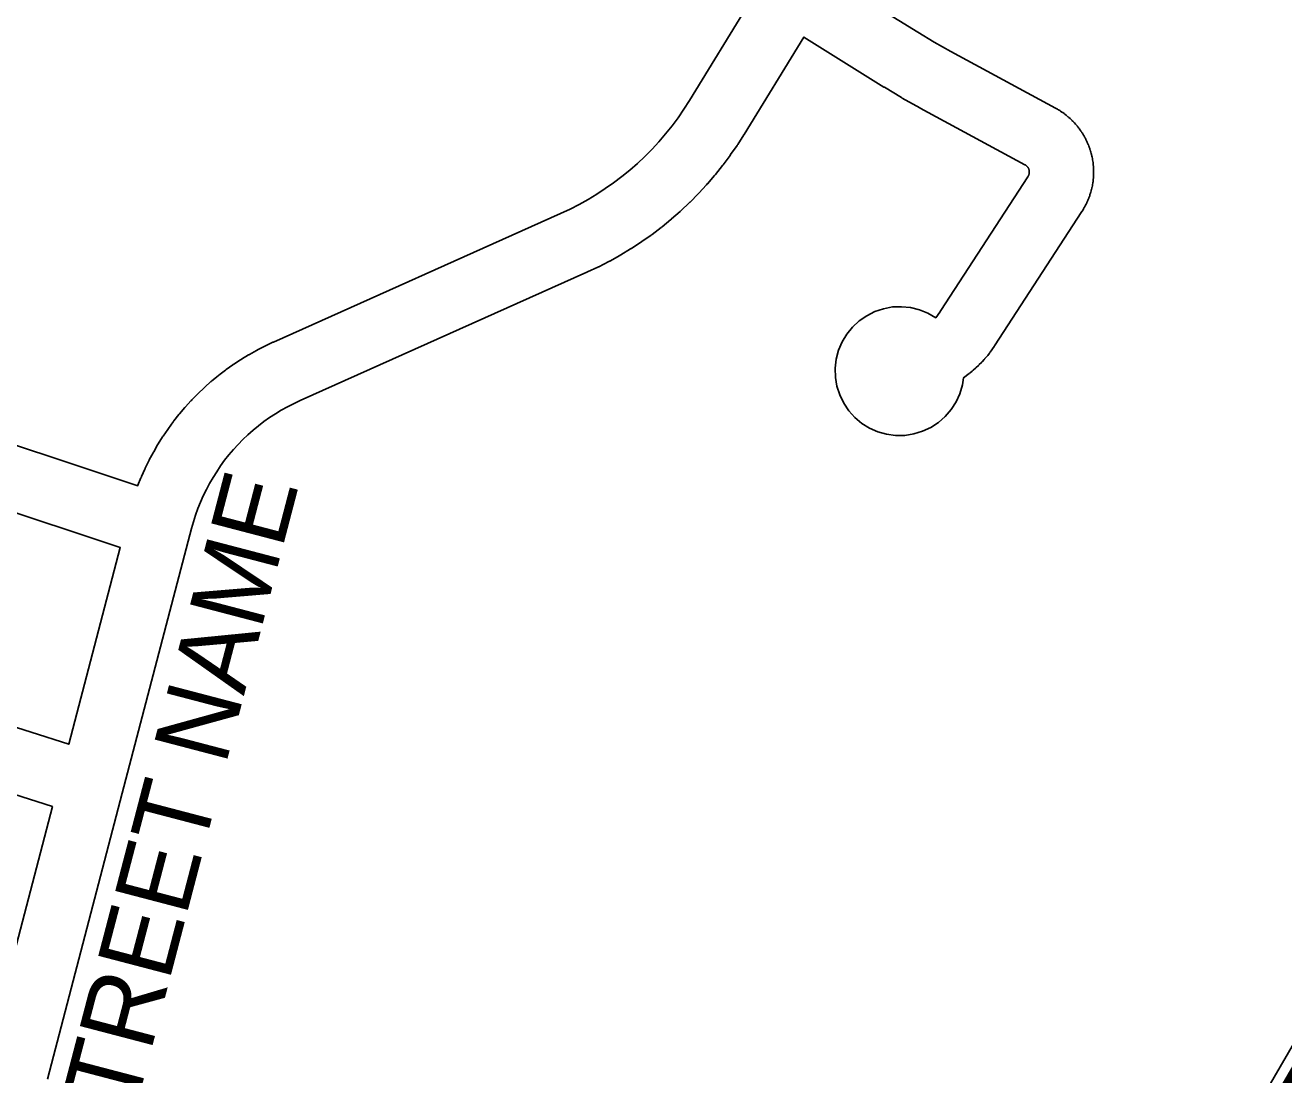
# Model space of a CAD drawing. Extents: x 599744 to 600217, y 4827560 to 4828065.
# Drawn here: x 599995.73 to 600007.45, y 4827978.51 to 4827988.28 of the extents above; entities that cross this region are included whole.
import ezdxf

# ---------------------------------------------------------------- set-up
doc = ezdxf.new("R2010")
doc.units = 0
doc.layers.add('G-ANNO-KEYP', color=7, linetype='Continuous')

msp = doc.modelspace()

# ---------------------------------------------------------------- linework, layer by layer
at = {"layer": 'G-ANNO-KEYP'}
for points in [[(600005.355, 4827987.49), (600005.353, 4827987.49), (600005.346, 4827987.496), (600005.334, 4827987.502), (600005.333, 4827987.502), (600005.329, 4827987.505), (600004.354, 4827988.032), (600004.198, 4827988.119), (600004.044, 4827988.212), (600003.298, 4827988.677), (600005.885, 4827992.881), (600006.372, 4827993.673)], [(600005.355, 4827974.888), (600005.664, 4827975.381), (600005.716, 4827975.467), (600005.764, 4827975.555), (600006.681, 4827977.304), (600006.685, 4827977.31), (600006.685, 4827977.312), (600006.748, 4827977.426), (600006.753, 4827977.433), (600006.753, 4827977.435), (600014.004, 4827989.912)], [(600002.476, 4827988.483), (600001.919, 4827987.578), (600001.866, 4827987.495), (600001.812, 4827987.417), (600001.756, 4827987.341), (600001.696, 4827987.266), (600001.634, 4827987.194), (600001.57, 4827987.125), (600001.503, 4827987.057), (600001.433, 4827986.992), (600001.362, 4827986.929), (600001.288, 4827986.869), (600001.212, 4827986.811), (600001.134, 4827986.757), (600001.055, 4827986.705), (600000.974, 4827986.655), (600000.89, 4827986.609), (600000.806, 4827986.566), (600000.717, 4827986.524), (599998.044, 4827985.329), (599998.042, 4827985.328), (599998.039, 4827985.327), (599997.971, 4827985.295), (599997.968, 4827985.292), (599997.962, 4827985.29), (599997.895, 4827985.256), (599997.891, 4827985.253), (599997.885, 4827985.251), (599997.82, 4827985.214), (599997.815, 4827985.211)], [(600001.567, 4827986.33), (600001.57, 4827986.331), (600001.654, 4827986.395), (600001.66, 4827986.4), (600001.663, 4827986.402), (600001.744, 4827986.469), (600001.75, 4827986.474), (600001.752, 4827986.475), (600001.832, 4827986.545), (600001.838, 4827986.551), (600001.84, 4827986.552), (600001.917, 4827986.624), (600001.923, 4827986.631), (600001.924, 4827986.632), (600001.999, 4827986.707), (600002.005, 4827986.714), (600002.006, 4827986.715), (600002.078, 4827986.792), (600002.084, 4827986.8), (600002.085, 4827986.8), (600002.153, 4827986.88), (600002.16, 4827986.888), (600002.16, 4827986.888), (600002.226, 4827986.971), (600002.229, 4827986.974), (600002.233, 4827986.979), (600002.296, 4827987.064), (600002.296, 4827987.064), (600002.302, 4827987.073), (600002.362, 4827987.159), (600002.362, 4827987.16), (600002.368, 4827987.168), (600002.425, 4827987.257), (600002.425, 4827987.258), (600002.428, 4827987.262), (600002.984, 4827988.167), (600003.73, 4827987.702), (600003.731, 4827987.702), (600003.734, 4827987.7), (600003.893, 4827987.604), (600003.895, 4827987.603), (600003.901, 4827987.599), (600004.063, 4827987.508), (600004.064, 4827987.508), (600004.067, 4827987.506), (600005.042, 4827986.979), (600005.047, 4827986.977), (600005.049, 4827986.975), (600005.051, 4827986.974), (600005.054, 4827986.972)], [(600005.614, 4827987.209), (600005.611, 4827987.213), (600005.609, 4827987.218), (600005.603, 4827987.23), (600005.599, 4827987.235), (600005.598, 4827987.24), (600005.591, 4827987.252), (600005.587, 4827987.256), (600005.585, 4827987.261), (600005.578, 4827987.272), (600005.574, 4827987.277), (600005.572, 4827987.281), (600005.565, 4827987.293), (600005.56, 4827987.297), (600005.559, 4827987.301), (600005.551, 4827987.312), (600005.546, 4827987.317), (600005.544, 4827987.321), (600005.536, 4827987.331), (600005.531, 4827987.337), (600005.529, 4827987.34), (600005.521, 4827987.35), (600005.515, 4827987.356), (600005.514, 4827987.358), (600005.505, 4827987.368), (600005.498, 4827987.374), (600005.497, 4827987.376), (600005.488, 4827987.386), (600005.481, 4827987.392), (600005.48, 4827987.393), (600005.471, 4827987.403), (600005.463, 4827987.409), (600005.463, 4827987.41), (600005.453, 4827987.419), (600005.445, 4827987.426), (600005.444, 4827987.426), (600005.434, 4827987.435), (600005.427, 4827987.44), (600005.426, 4827987.441), (600005.416, 4827987.449), (600005.416, 4827987.449), (600005.416, 4827987.449), (600005.415, 4827987.449), (600005.415, 4827987.449), (600005.407, 4827987.456), (600005.396, 4827987.464), (600005.395, 4827987.464), (600005.387, 4827987.47), (600005.375, 4827987.477), (600005.374, 4827987.478), (600005.367, 4827987.483), (600005.355, 4827987.49)], [(600005.677, 4827986.819), (600005.678, 4827986.832), (600005.678, 4827986.84), (600005.68, 4827986.843), (600005.681, 4827986.856), (600005.681, 4827986.865), (600005.682, 4827986.867), (600005.682, 4827986.88), (600005.682, 4827986.889), (600005.683, 4827986.891), (600005.683, 4827986.905), (600005.683, 4827986.914), (600005.683, 4827986.915), (600005.683, 4827986.929), (600005.682, 4827986.939), (600005.682, 4827986.94), (600005.682, 4827986.953), (600005.681, 4827986.963), (600005.681, 4827986.964), (600005.68, 4827986.977), (600005.679, 4827986.988), (600005.679, 4827986.988), (600005.677, 4827987.001), (600005.677, 4827987.001), (600005.675, 4827987.012), (600005.673, 4827987.025), (600005.673, 4827987.026), (600005.671, 4827987.036), (600005.669, 4827987.049), (600005.668, 4827987.05), (600005.667, 4827987.059), (600005.663, 4827987.073), (600005.663, 4827987.074), (600005.661, 4827987.083), (600005.657, 4827987.096), (600005.656, 4827987.098), (600005.654, 4827987.106), (600005.65, 4827987.119), (600005.649, 4827987.121), (600005.647, 4827987.129), (600005.642, 4827987.142), (600005.641, 4827987.145), (600005.639, 4827987.152), (600005.634, 4827987.165), (600005.631, 4827987.168), (600005.629, 4827987.175), (600005.624, 4827987.187), (600005.622, 4827987.19), (600005.62, 4827987.197), (600005.614, 4827987.209)], [(600005.054, 4827986.972), (600005.056, 4827986.97), (600005.058, 4827986.969), (600005.06, 4827986.967), (600005.062, 4827986.965), (600005.064, 4827986.963), (600005.066, 4827986.961), (600005.067, 4827986.959), (600005.069, 4827986.957), (600005.07, 4827986.955), (600005.072, 4827986.952), (600005.074, 4827986.95), (600005.075, 4827986.948), (600005.076, 4827986.945), (600005.077, 4827986.943), (600005.078, 4827986.941), (600005.079, 4827986.938), (600005.08, 4827986.935), (600005.081, 4827986.933), (600005.082, 4827986.93), (600005.083, 4827986.927), (600005.083, 4827986.925), (600005.083, 4827986.922), (600005.084, 4827986.92), (600005.084, 4827986.916), (600005.084, 4827986.914), (600005.084, 4827986.911), (600005.084, 4827986.909), (600005.084, 4827986.906), (600005.084, 4827986.903), (600005.083, 4827986.9), (600005.083, 4827986.898), (600005.082, 4827986.895), (600005.082, 4827986.892), (600005.081, 4827986.89), (600005.08, 4827986.887), (600005.079, 4827986.885), (600005.078, 4827986.882), (600005.077, 4827986.88), (600005.076, 4827986.877), (600005.075, 4827986.875), (600005.073, 4827986.872), (600005.071, 4827986.868), (600004.26, 4827985.622), (600004.249, 4827985.606), (600004.212, 4827985.555), (600004.139, 4827985.597), (600004.06, 4827985.629), (600003.978, 4827985.65), (600003.893, 4827985.658), (600003.808, 4827985.655), (600003.725, 4827985.639)], [(600004.671, 4827985.175), (600004.689, 4827985.195), (600004.696, 4827985.204), (600004.696, 4827985.204), (600004.713, 4827985.226), (600004.714, 4827985.227), (600004.719, 4827985.234), (600004.736, 4827985.257), (600004.736, 4827985.257), (600004.742, 4827985.266), (600004.757, 4827985.288), (600004.757, 4827985.289), (600004.76, 4827985.293), (600005.574, 4827986.544), (600005.574, 4827986.544), (600005.577, 4827986.548), (600005.584, 4827986.56), (600005.584, 4827986.561), (600005.59, 4827986.569), (600005.596, 4827986.581), (600005.597, 4827986.583), (600005.601, 4827986.59), (600005.608, 4827986.602), (600005.608, 4827986.604), (600005.613, 4827986.612), (600005.619, 4827986.624), (600005.619, 4827986.627), (600005.623, 4827986.633), (600005.628, 4827986.646), (600005.629, 4827986.649), (600005.633, 4827986.656), (600005.638, 4827986.668), (600005.638, 4827986.672), (600005.641, 4827986.678), (600005.646, 4827986.691), (600005.646, 4827986.695), (600005.649, 4827986.701), (600005.653, 4827986.714), (600005.654, 4827986.719), (600005.656, 4827986.724), (600005.66, 4827986.737), (600005.661, 4827986.743), (600005.663, 4827986.748), (600005.666, 4827986.761), (600005.666, 4827986.767), (600005.668, 4827986.771), (600005.671, 4827986.784), (600005.671, 4827986.791), (600005.673, 4827986.795), (600005.675, 4827986.808), (600005.675, 4827986.815), (600005.677, 4827986.819)], [(599995.94, 4827978.468), (599996.636, 4827981.129), (599997.266, 4827983.535), (599997.266, 4827983.535), (599997.281, 4827983.592), (599997.299, 4827983.656), (599997.318, 4827983.718), (599997.34, 4827983.779), (599997.364, 4827983.838), (599997.39, 4827983.897), (599997.419, 4827983.955), (599997.449, 4827984.012), (599997.481, 4827984.068), (599997.515, 4827984.122), (599997.551, 4827984.176), (599997.589, 4827984.228), (599997.629, 4827984.278), (599997.671, 4827984.327), (599997.714, 4827984.375), (599997.759, 4827984.421), (599997.806, 4827984.466), (599997.854, 4827984.508), (599997.904, 4827984.549), (599997.955, 4827984.588), (599998.008, 4827984.626), (599998.062, 4827984.661), (599998.117, 4827984.695), (599998.173, 4827984.726), (599998.23, 4827984.755), (599998.291, 4827984.784), (600000.964, 4827985.979), (600000.966, 4827985.98), (600000.969, 4827985.981), (600001.064, 4827986.026), (600001.068, 4827986.028), (600001.074, 4827986.03), (600001.168, 4827986.078), (600001.172, 4827986.082), (600001.177, 4827986.083), (600001.27, 4827986.135), (600001.274, 4827986.138), (600001.279, 4827986.14), (600001.369, 4827986.195), (600001.374, 4827986.199), (600001.378, 4827986.2), (600001.467, 4827986.258), (600001.471, 4827986.263), (600001.475, 4827986.264), (600001.562, 4827986.325), (600001.567, 4827986.33)], [(600003.725, 4827985.639), (600003.645, 4827985.612), (600003.569, 4827985.574), (600003.499, 4827985.526), (600003.437, 4827985.468), (600003.384, 4827985.402), (600003.34, 4827985.33), (600003.307, 4827985.252), (600003.286, 4827985.17), (600003.276, 4827985.085), (600003.278, 4827985), (600003.292, 4827984.917), (600003.318, 4827984.836), (600003.355, 4827984.76), (600003.402, 4827984.689), (600003.459, 4827984.626), (600003.524, 4827984.572), (600003.596, 4827984.527), (600003.674, 4827984.493), (600003.755, 4827984.47), (600003.839, 4827984.459), (600003.924, 4827984.46), (600004.008, 4827984.473), (600004.089, 4827984.498), (600004.166, 4827984.534), (600004.237, 4827984.58), (600004.301, 4827984.636), (600004.356, 4827984.7), (600004.402, 4827984.771), (600004.437, 4827984.848), (600004.461, 4827984.93), (600004.472, 4827984.997), (600004.523, 4827985.035), (600004.529, 4827985.041), (600004.532, 4827985.042), (600004.553, 4827985.059), (600004.559, 4827985.065), (600004.561, 4827985.066), (600004.582, 4827985.085), (600004.588, 4827985.091), (600004.59, 4827985.092), (600004.61, 4827985.111), (600004.617, 4827985.118), (600004.618, 4827985.119), (600004.637, 4827985.138), (600004.644, 4827985.146), (600004.645, 4827985.146), (600004.664, 4827985.166), (600004.67, 4827985.174), (600004.671, 4827985.175)], [(599996.849, 4827984.151), (599996.845, 4827984.145), (599996.815, 4827984.076), (599996.814, 4827984.072), (599996.81, 4827984.066), (599996.782, 4827983.996), (599996.782, 4827983.992), (599996.781, 4827983.991), (599993.054, 4827985.229)], [(599997.815, 4827985.211), (599997.81, 4827985.209), (599997.746, 4827985.17), (599997.742, 4827985.166), (599997.737, 4827985.164), (599997.674, 4827985.123), (599997.67, 4827985.119), (599997.666, 4827985.117), (599997.604, 4827985.073), (599997.599, 4827985.069), (599997.596, 4827985.067), (599997.536, 4827985.022), (599997.531, 4827985.016), (599997.528, 4827985.015), (599997.47, 4827984.967), (599997.464, 4827984.961), (599997.461, 4827984.96), (599997.405, 4827984.91), (599997.399, 4827984.904), (599997.397, 4827984.903), (599997.343, 4827984.851), (599997.337, 4827984.845), (599997.335, 4827984.844), (599997.283, 4827984.79), (599997.276, 4827984.783), (599997.275, 4827984.782), (599997.225, 4827984.727), (599997.218, 4827984.719), (599997.218, 4827984.719), (599997.169, 4827984.661), (599997.162, 4827984.653), (599997.162, 4827984.653), (599997.116, 4827984.594), (599997.115, 4827984.593), (599997.109, 4827984.586), (599997.065, 4827984.525), (599997.065, 4827984.524), (599997.059, 4827984.516), (599997.017, 4827984.454), (599997.016, 4827984.453), (599997.011, 4827984.445), (599996.971, 4827984.381), (599996.97, 4827984.38), (599996.965, 4827984.372), (599996.928, 4827984.307), (599996.927, 4827984.305), (599996.922, 4827984.298), (599996.887, 4827984.231), (599996.887, 4827984.229), (599996.882, 4827984.222), (599996.849, 4827984.154), (599996.849, 4827984.151)], [(599992.868, 4827984.66), (599996.616, 4827983.415), (599996.137, 4827981.585), (599994.73, 4827982.031)], [(599994.552, 4827981.46), (599995.985, 4827981.005), (599995.425, 4827978.865)]]:
    msp.add_lwpolyline(points, dxfattribs=at)

# ---------------------------------------------------------------- texts
for s, rotation, p in [('STREET NAME', 75.3405, (599996.596, 4827977.553)), ('STREET A', 59.8386, (600007.671, 4827977.434))]:
    msp.add_text(s, height=0.7, rotation=rotation, dxfattribs=at).set_placement(p)

doc.saveas('drawing.dxf')
